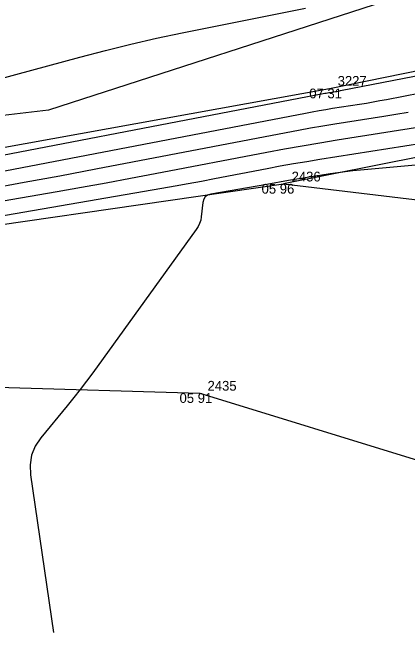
# Model space of a CAD drawing. Extents: x -703403 to -701924, y -1022520 to -1021856.
# Drawn here: x -702462.39 to -702451.05, y -1022349.49 to -1022331.73 of the extents above; entities that cross this region are included whole.
import ezdxf

# ---------------------------------------------------------------- set-up
doc = ezdxf.new("R2010")
doc.units = 0
for name, color, linetype in [('Ex_Major Contours', 7, 'Continuous'), ('Ex_Minor Contours', 7, 'Continuous'), ('Z_body', 7, 'Continuous'), ('Z_body_cisla', 7, 'Continuous'), ('Z_body_vysky_redukovane', 7, 'Continuous'), ('Z_hrany_paty', 7, 'Continuous'), ('Z_katastr_hranice', 7, 'Continuous'), ('Z_pole_rozhranni', 7, 'Continuous')]:
    doc.layers.add(name, color=color, linetype=linetype)

# ---------------------------------------------------------------- blocks, each defined once
blk = doc.blocks.new('POINT_DISPLAY')
blk.add_line((0, 0), (0, 0))

msp = doc.modelspace()

# ---------------------------------------------------------------- linework, layer by layer
at = {"layer": 'Ex_Major Contours'}
for points in [[(-702462.813, -1022336.3), (-702453.979, -1022334.611), (-702453.786, -1022334.575), (-702453.593, -1022334.54), (-702453.399, -1022334.507), (-702453.205, -1022334.476), (-702452.43, -1022334.355), (-702452.236, -1022334.324), (-702452.043, -1022334.291), (-702451.85, -1022334.256), (-702451.657, -1022334.219), (-702448.248, -1022333.556)], [(-702449.051, -1022335.94), (-702452.406, -1022336.249), (-702452.623, -1022336.27), (-702452.841, -1022336.295), (-702453.057, -1022336.324), (-702453.274, -1022336.356), (-702454.466, -1022336.543), (-702454.519, -1022336.551), (-702454.571, -1022336.56), (-702454.623, -1022336.569), (-702454.675, -1022336.579), (-702454.883, -1022336.619), (-702454.935, -1022336.629), (-702454.987, -1022336.638), (-702455.039, -1022336.647), (-702455.091, -1022336.657), (-702456.7, -1022336.934), (-702456.789, -1022336.962), (-702456.856, -1022337.011), (-702456.901, -1022337.081), (-702456.924, -1022337.172), (-702456.969, -1022337.579), (-702456.987, -1022337.678), (-702457.016, -1022337.773), (-702457.058, -1022337.862), (-702457.112, -1022337.948), (-702460.083, -1022342.046), (-702460.26, -1022342.286), (-702460.441, -1022342.524), (-702460.625, -1022342.759), (-702460.813, -1022342.991), (-702461.572, -1022343.913), (-702461.733, -1022344.152), (-702461.835, -1022344.407), (-702461.879, -1022344.679), (-702461.866, -1022344.966), (-702461.211, -1022349.486)]]:
    msp.add_lwpolyline(points, dxfattribs=at)
at = {"layer": 'Ex_Minor Contours'}
for points in [[(-702468.012, -1022335.053), (-702460.449, -1022333.007), (-702459.72, -1022332.816), (-702458.988, -1022332.637), (-702458.253, -1022332.471), (-702457.515, -1022332.317), (-702453.977, -1022331.609)], [(-702466.161, -1022336.481), (-702453.423, -1022334.046), (-702453.386, -1022334.039), (-702453.349, -1022334.032), (-702453.311, -1022334.026), (-702453.274, -1022334.02), (-702453.124, -1022333.996), (-702453.086, -1022333.99), (-702453.049, -1022333.984), (-702453.011, -1022333.977), (-702452.974, -1022333.97), (-702448.139, -1022333.03)], [(-702451.037, -1022334.598), (-702451.387, -1022334.657), (-702451.736, -1022334.714), (-702453.137, -1022334.933), (-702453.487, -1022334.989), (-702453.837, -1022335.048), (-702454.185, -1022335.11), (-702454.534, -1022335.176), (-702459.996, -1022336.22), (-702461.023, -1022336.414), (-702462.051, -1022336.603), (-702463.079, -1022336.788)], [(-702450.461, -1022334.982), (-702453.069, -1022335.39), (-702453.575, -1022335.471), (-702454.081, -1022335.557), (-702454.585, -1022335.646), (-702455.089, -1022335.741), (-702458.292, -1022336.353), (-702458.994, -1022336.486), (-702459.696, -1022336.615), (-702460.399, -1022336.741), (-702461.103, -1022336.864), (-702473.556, -1022339.012)], [(-702470.78, -1022338.948), (-702458.097, -1022336.76), (-702457.719, -1022336.694), (-702457.341, -1022336.627), (-702456.964, -1022336.557), (-702456.587, -1022336.486), (-702455.08, -1022336.198), (-702454.703, -1022336.127), (-702454.325, -1022336.06), (-702453.947, -1022335.996), (-702453.568, -1022335.935), (-702449.185, -1022335.249)]]:
    msp.add_lwpolyline(points, dxfattribs=at)
at = {"layer": 'Z_hrany_paty'}
for p, q in [((-702453.29, -1022333.91), (-702448.1, -1022332.84)), ((-702468.17, -1022336.59), (-702453.29, -1022333.91)), ((-702448.42, -1022335.41), (-702454.61, -1022336.64)), ((-702475.23, -1022339.6), (-702454.61, -1022336.64)), ((-702454.61, -1022336.64), (-702448.57, -1022337.36))]:
    msp.add_line(p, q, dxfattribs=at)
at = {"layer": 'Z_katastr_hranice'}
for p, q in [((-702432.63, -1022325.24), (-702461.35, -1022334.53)), ((-702461.35, -1022334.53), (-702512.42, -1022340.39))]:
    msp.add_line(p, q, dxfattribs=at)
at = {"layer": 'Z_pole_rozhranni'}
for p, q in [((-702466.52, -1022342.35), (-702457.01, -1022342.63)), ((-702457.01, -1022342.63), (-702445.18, -1022346.28))]:
    msp.add_line(p, q, dxfattribs=at)

# ---------------------------------------------------------------- block references
at = {"layer": 'Z_body'}
for p in [(-702453.29, -1022333.91), (-702454.61, -1022336.64), (-702457.01, -1022342.63)]:
    msp.add_blockref('POINT_DISPLAY', p, dxfattribs=at)

# ---------------------------------------------------------------- texts
at = {"layer": 'Z_body_cisla'}
for s, p in [('3227', (-702453.06, -1022333.83)), ('2436', (-702454.38, -1022336.57)), ('2435', (-702456.79, -1022342.56))]:
    msp.add_text(s, height=0.28, dxfattribs=at).set_placement(p)
at = {"layer": 'Z_body_vysky_redukovane'}
for s, p in [('07 31', (-702453.873, -1022334.19)), ('05 96', (-702455.24, -1022336.92)), ('05 91', (-702457.593, -1022342.91))]:
    msp.add_text(s, height=0.28, dxfattribs=at).set_placement(p)

doc.saveas('drawing.dxf')
